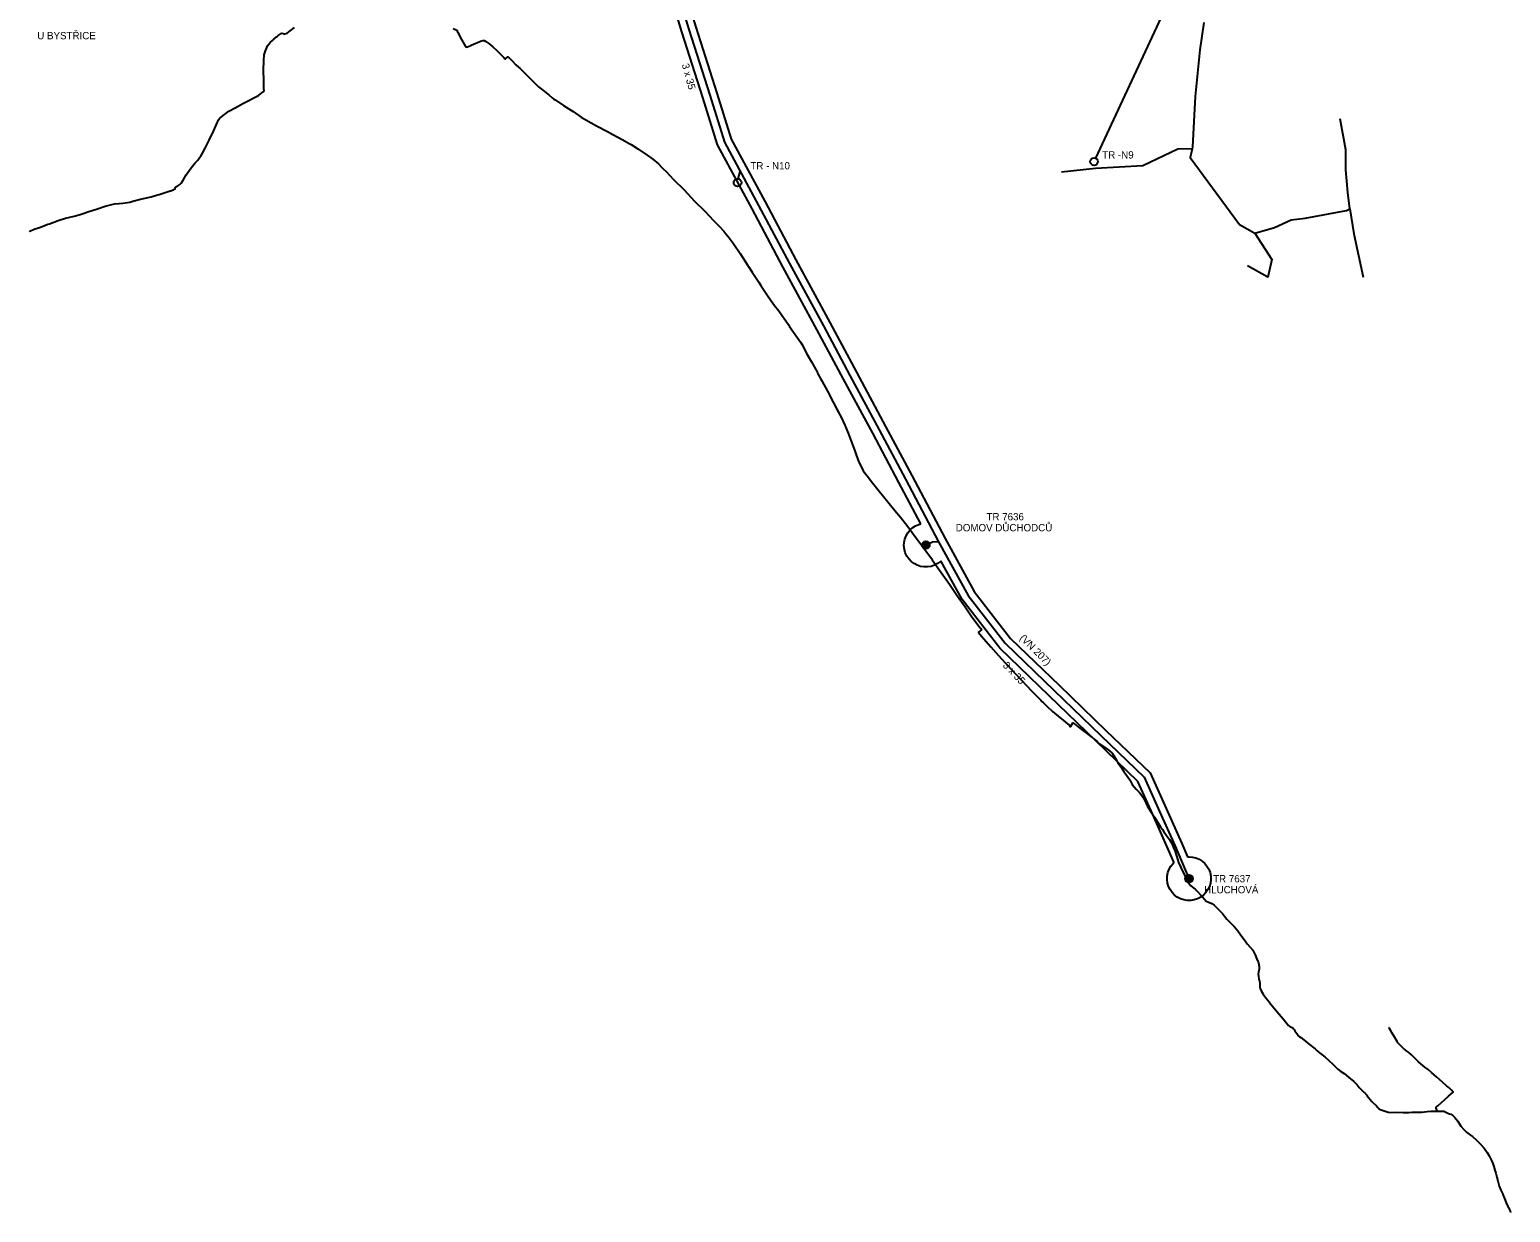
# Model space of a CAD drawing. Extents: x -439095 to -431527, y -1129525 to -1119219.
# Drawn here: x -438464 to -436435, y -1126025 to -1124404 of the extents above; entities that cross this region are included whole.
import ezdxf

# ---------------------------------------------------------------- set-up
doc = ezdxf.new("R2010")
doc.units = 0
for name, color, linetype in [('Hranice reseneho uzemi', 7, 'Continuous'), ('UZEMNI REZERVA', 7, 'Continuous'), ('Vrstva 11', 7, 'Continuous'), ('Vrstva 13', 7, 'Continuous'), ('Vrstva 19', 7, 'Continuous'), ('Vrstva 21', 7, 'Continuous'), ('ZU', 7, 'Continuous')]:
    doc.layers.add(name, color=color, linetype=linetype)

msp = doc.modelspace()

# ---------------------------------------------------------------- linework, layer by layer
at = {"layer": 'Hranice reseneho uzemi'}
msp.add_line((-437493.3, -1124608.4), (-437490.5, -1124598.1), dxfattribs=at)
for points in [[(-437594, -1124294.9), (-437561.1, -1124403.7), (-437532, -1124493.8), (-437512.2, -1124558.1), (-437465.3, -1124644.8), (-437423.1, -1124724.2), (-437376.5, -1124809.9), (-437340.2, -1124878), (-437300.2, -1124952.4), (-437264.2, -1125019.8), (-437218.6, -1125106), (-437178.2, -1125179.2), (-437127.5, -1125244.7), (-437060.5, -1125309.5), (-436996.4, -1125371.4), (-436937.2, -1125428.2), (-436916.2, -1125475.5), (-436894.8, -1125522.9), (-436894.8, -1125522.9), (-436875.7, -1125567.4), (-436875.4, -1125567.4), (-436875.4, -1125567.5)], [(-436908.2, -1124303.4), (-436911.1, -1124380.9), (-437003.6, -1124579.9)], [(-437218.6, -1125106), (-437226.9, -1125106.3), (-437236.2, -1125110.3)]]:
    msp.add_lwpolyline(points, dxfattribs=at)
at = {"layer": 'UZEMNI REZERVA'}
for points in [[(-438464.1, -1124680.4), (-438463.6, -1124680.2), (-438457.8, -1124677.4), (-438449.3, -1124674.4), (-438439.2, -1124670.7), (-438436.8, -1124669.8), (-438430.8, -1124667.6), (-438425, -1124665.5), (-438414.8, -1124662.4), (-438403.1, -1124659.3), (-438395, -1124657), (-438390.8, -1124655.7), (-438384.2, -1124653.6), (-438371, -1124649.4), (-438360.7, -1124646), (-438347.9, -1124642.8), (-438341.6, -1124642), (-438336.4, -1124641.7), (-438326.7, -1124640.1), (-438322.5, -1124639), (-438312.1, -1124636.4), (-438297.6, -1124632.8), (-438290, -1124630.8), (-438286.5, -1124629.8), (-438277, -1124626.8), (-438267, -1124623.4), (-438265.4, -1124622.7), (-438264.8, -1124621.9), (-438264.6, -1124620.2), (-438263.7, -1124619.3), (-438261, -1124618.1), (-438258.3, -1124616.3), (-438256.2, -1124614), (-438253.7, -1124610.2), (-438249.5, -1124603), (-438242.8, -1124593.1), (-438237.3, -1124586.3), (-438233.5, -1124582.9), (-438230.8, -1124578.8), (-438229, -1124576.2), (-438227.1, -1124573.3), (-438223.4, -1124566.5), (-438218.2, -1124555.5), (-438211.6, -1124542.1), (-438207.3, -1124531.7), (-438206.4, -1124529.7), (-438205.4, -1124527.3), (-438203.4, -1124525.1), (-438201.1, -1124523.3), (-438197.2, -1124520), (-438191, -1124515.8), (-438182.3, -1124511.2), (-438171, -1124504.7), (-438163, -1124500.7), (-438161.9, -1124500), (-438158.9, -1124498.2), (-438150.7, -1124494.1), (-438145.9, -1124490.6), (-438144.2, -1124489.1), (-438142.9, -1124487.3), (-438143, -1124485.4), (-438143, -1124482.6), (-438143, -1124478.4), (-438143, -1124473.1), (-438143.6, -1124460), (-438143.3, -1124445.6), (-438142.5, -1124438.2), (-438141.1, -1124433.1), (-438138, -1124426.3), (-438134.5, -1124421.7), (-438131, -1124418.1), (-438129.4, -1124417), (-438125.8, -1124413.9), (-438125, -1124413.2), (-438123.4, -1124411.8), (-438119.3, -1124409.2), (-438118.3, -1124408.8), (-438116.9, -1124409.3), (-438115.6, -1124410.1), (-438114.2, -1124409.8), (-438111.2, -1124408.5), (-438107, -1124405.6), (-438101.3, -1124400.9)], [(-437883.8, -1124402.3), (-437878.9, -1124404.6), (-437878.1, -1124405.8), (-437877.3, -1124407.3), (-437874.3, -1124414.2), (-437866.8, -1124427.2), (-437865.9, -1124427.5), (-437865.1, -1124427.7), (-437864.4, -1124427.4), (-437864.3, -1124427.4), (-437859.4, -1124425.6), (-437859, -1124425.3), (-437858.9, -1124425.3), (-437847.1, -1124420.1), (-437847, -1124420.1), (-437846.9, -1124420), (-437846.6, -1124419.9), (-437846.2, -1124419.7), (-437842.9, -1124418.7), (-437841.5, -1124418.9), (-437839.1, -1124420.3), (-437835.1, -1124423), (-437829.3, -1124427.5), (-437823.9, -1124432.5), (-437818.7, -1124437.6), (-437814.3, -1124442), (-437812.8, -1124443.7), (-437812.4, -1124444), (-437812.1, -1124443.9), (-437809, -1124441), (-437808.7, -1124441), (-437808.1, -1124441.5), (-437807.9, -1124441.7), (-437803, -1124446.6), (-437797.7, -1124451.9), (-437794.2, -1124455.2), (-437792.4, -1124456.9), (-437786.9, -1124462.1), (-437781.5, -1124467.5), (-437775.9, -1124473.1), (-437771.6, -1124477.5), (-437766.7, -1124482.2), (-437761.5, -1124486.5), (-437756.5, -1124490.5), (-437752.7, -1124493.4), (-437748.3, -1124497.2), (-437745.8, -1124499), (-437744.2, -1124500), (-437732.4, -1124507.7), (-437721.6, -1124514.8), (-437719.4, -1124516.2), (-437708.2, -1124523.7), (-437702.1, -1124527.3), (-437687.6, -1124535.5), (-437672.1, -1124543.7), (-437665.2, -1124547.4), (-437658.1, -1124551.2), (-437652.4, -1124554.3), (-437641.7, -1124560.5), (-437639.9, -1124561.5), (-437630.7, -1124567.4), (-437618.1, -1124576.1), (-437610.4, -1124581.6), (-437602.6, -1124588), (-437597.8, -1124592.8), (-437596.1, -1124594.5), (-437592.1, -1124598.5), (-437581.7, -1124609.3), (-437567.4, -1124623.6), (-437553, -1124638.8), (-437540, -1124651.9), (-437532.1, -1124660), (-437527.8, -1124664.5), (-437518.9, -1124673.7), (-437513, -1124680.2), (-437510.1, -1124683.8), (-437507, -1124687.6), (-437500, -1124696.7), (-437499.3, -1124697.7), (-437490.6, -1124710.5), (-437480.2, -1124727), (-437479.2, -1124728.5), (-437474, -1124736.3), (-437465.2, -1124749.9), (-437462.2, -1124754.5), (-437454, -1124766.7), (-437448.1, -1124775.5), (-437443.4, -1124781.8), (-437437.7, -1124789.4), (-437424.1, -1124809), (-437423, -1124810.5), (-437411.9, -1124826.3), (-437407.5, -1124832.6), (-437404.7, -1124837.2), (-437400.2, -1124846.8), (-437392.8, -1124859), (-437384.8, -1124873.9), (-437384, -1124875.4), (-437380, -1124882.8), (-437378.6, -1124885.3), (-437371.1, -1124899.5), (-437362.7, -1124915.2), (-437357.5, -1124925), (-437356.5, -1124927), (-437356.1, -1124927.7), (-437352.3, -1124935), (-437347.3, -1124945.8), (-437342.4, -1124956.9), (-437335.9, -1124975), (-437333.6, -1124981.2), (-437331.6, -1124986.7), (-437327.8, -1124996.5), (-437326, -1125000), (-437321.9, -1125008.3), (-437314.8, -1125017.8), (-437314.8, -1125017.8), (-437314.8, -1125017.8), (-437312.5, -1125020.9), (-437309.4, -1125024.8), (-437300.1, -1125036.3), (-437288.4, -1125050.8), (-437278.6, -1125062.7), (-437270.9, -1125071.9), (-437262, -1125083.2), (-437254.7, -1125093.1), (-437249.7, -1125099.7), (-437238.8, -1125114.5), (-437228.5, -1125128.8), (-437227.5, -1125130.3), (-437215.3, -1125147.8), (-437203.9, -1125163.9), (-437192.8, -1125180.2), (-437182.5, -1125195.1), (-437173, -1125208.6), (-437161.7, -1125223.8), (-437160.9, -1125224.5), (-437160.9, -1125224.5), (-437159.7, -1125226.2), (-437159.9, -1125226.3), (-437163.9, -1125229.5), (-437164.2, -1125229.8), (-437164.1, -1125229.9), (-437159.8, -1125234.9), (-437153.4, -1125242.2), (-437146.9, -1125249.8), (-437140.5, -1125257.3), (-437132.7, -1125266.3), (-437126.7, -1125272.4), (-437125.2, -1125274), (-437118.6, -1125280.7), (-437112.4, -1125287.7), (-437104.9, -1125295.5), (-437098.2, -1125302.5), (-437090.9, -1125310.3), (-437084.2, -1125317.5), (-437078.7, -1125322.9), (-437077.1, -1125324.4), (-437075.4, -1125326.2), (-437070.6, -1125331.1), (-437062.7, -1125338.2), (-437054.8, -1125344.8), (-437047.7, -1125350.7), (-437039.7, -1125356.9), (-437039.4, -1125358), (-437038.8, -1125358.8), (-437038.2, -1125359), (-437038.1, -1125359), (-437037.7, -1125358.9), (-437037.4, -1125358.6), (-437034.7, -1125353.8), (-437034.6, -1125353.7), (-437032.1, -1125355.5), (-437022.9, -1125362.8), (-437018.1, -1125366.5), (-437018, -1125366.6), (-437008.1, -1125374.1), (-437001.5, -1125379.4), (-437000.8, -1125380.1), (-437000.2, -1125381.2), (-436999, -1125382.2), (-436992.9, -1125386.2), (-436988.2, -1125389.7), (-436984.4, -1125392.2), (-436981.1, -1125395.3), (-436978.5, -1125399), (-436975.4, -1125404), (-436972.9, -1125408.6), (-436968.4, -1125414.8), (-436964.8, -1125420.6), (-436961.2, -1125425.7), (-436956.5, -1125432.1), (-436955.3, -1125434.5), (-436955.3, -1125434.5), (-436953.3, -1125438.3), (-436948.2, -1125444.6), (-436944, -1125449), (-436941.6, -1125451.5), (-436938.6, -1125456.1), (-436935.5, -1125461.3), (-436933, -1125467.5), (-436928.4, -1125474.7), (-436922.9, -1125483.1), (-436918.3, -1125490.4), (-436914.5, -1125496.5), (-436912.1, -1125500), (-436909.9, -1125503.3), (-436908.3, -1125505.7), (-436906.6, -1125508.2), (-436902.5, -1125513.8), (-436899.4, -1125518.2), (-436897.2, -1125523.6), (-436895.2, -1125529.3), (-436894.8, -1125530.3), (-436892.8, -1125536.3), (-436889.8, -1125545.2), (-436886.8, -1125551.9), (-436884.2, -1125557.9), (-436881.1, -1125564), (-436879.6, -1125568), (-436875, -1125575.1), (-436873.7, -1125577), (-436870.7, -1125579.2), (-436870.7, -1125579.2), (-436867.3, -1125581.6), (-436856.5, -1125592.7), (-436852.1, -1125598.2), (-436849.7, -1125599.2), (-436844.4, -1125601.6), (-436841.1, -1125603.7), (-436836.2, -1125608.6), (-436829.8, -1125615.2), (-436827, -1125618.8), (-436823.6, -1125623), (-436819.1, -1125627.6), (-436813.3, -1125633.4), (-436808.8, -1125638.9), (-436803.4, -1125646.6), (-436798.8, -1125652.5), (-436796.9, -1125655.2), (-436795.6, -1125657.1), (-436791.6, -1125661.1), (-436788.3, -1125665.4), (-436785, -1125672), (-436782.5, -1125677.7), (-436781.8, -1125679.3), (-436780.6, -1125682.9), (-436779.4, -1125687.8), (-436779.6, -1125691.5), (-436780.3, -1125695.6), (-436780.8, -1125698.4), (-436780.4, -1125701.3), (-436780.1, -1125704.1), (-436779.8, -1125705.7), (-436779.1, -1125707.6), (-436778.7, -1125711.7), (-436778.4, -1125716), (-436778.2, -1125717.8), (-436776.9, -1125721.3), (-436774.2, -1125725.6), (-436770.3, -1125730.9), (-436767.9, -1125733.7), (-436765.9, -1125736.3), (-436763.8, -1125739), (-436761.2, -1125742.2), (-436754.6, -1125749.9), (-436746.8, -1125759.5), (-436739.2, -1125768.6), (-436737.1, -1125770.4), (-436735.2, -1125770.8), (-436733.3, -1125772), (-436732.5, -1125773.1), (-436731.7, -1125774.2), (-436730.8, -1125776.1), (-436727.8, -1125779.8), (-436726.3, -1125782.2), (-436724.8, -1125783.6), (-436722.2, -1125784.9), (-436715.8, -1125790.1), (-436712.2, -1125793.2), (-436702.9, -1125800.7), (-436700, -1125803.3), (-436696.9, -1125806.2), (-436689.6, -1125811.8), (-436684.2, -1125816.4), (-436678.1, -1125821.9), (-436675.4, -1125824.7), (-436674.2, -1125826), (-436671.9, -1125828.3), (-436667.4, -1125831.6), (-436662.9, -1125834.6), (-436657.1, -1125839.4), (-436649.9, -1125845.6), (-436645.4, -1125850), (-436642.4, -1125853.7), (-436639.2, -1125856.8), (-436636.1, -1125859.8), (-436635.8, -1125860.1), (-436632.1, -1125864), (-436631.4, -1125865), (-436629.5, -1125867.5), (-436625, -1125872.9), (-436623.8, -1125874.1), (-436619.4, -1125878.2), (-436617, -1125880.9), (-436615.6, -1125882.6), (-436615.4, -1125882.7), (-436614.4, -1125883.4), (-436612.4, -1125884.3), (-436608.4, -1125885.8), (-436605.3, -1125886.6), (-436602.7, -1125887.4), (-436599.2, -1125887.8), (-436591.3, -1125887.6), (-436582.4, -1125887.8), (-436575.7, -1125887.7), (-436575.6, -1125887.7), (-436574.4, -1125887.7), (-436570.1, -1125887.6), (-436564, -1125887.5), (-436556.4, -1125887.3), (-436549.2, -1125886.7), (-436544.4, -1125886.1), (-436541.8, -1125886.1), (-436536, -1125885.9), (-436533.6, -1125885.9), (-436526.5, -1125885.9), (-436525.6, -1125886.3), (-436520.8, -1125888.7), (-436518.6, -1125889.8), (-436517, -1125890.2), (-436514.1, -1125891.9), (-436511.5, -1125894.5), (-436507.4, -1125899.9), (-436503, -1125906.8), (-436499.2, -1125911.2), (-436495.2, -1125914.9), (-436491.7, -1125917.4), (-436489.9, -1125918.8), (-436487.3, -1125920.9), (-436481.8, -1125925.9), (-436476.6, -1125930.8), (-436471.4, -1125936.6), (-436466.9, -1125942.9), (-436464.5, -1125947.1), (-436463.2, -1125950), (-436460.9, -1125954.6), (-436459.4, -1125957.9), (-436458, -1125961.9), (-436456.5, -1125966.8), (-436455.3, -1125971.2), (-436453.9, -1125976.4), (-436452.4, -1125981.6), (-436450.5, -1125989), (-436448.5, -1125994.4), (-436445.6, -1126000), (-436445.5, -1126000.1), (-436443.2, -1126005.6), (-436440.9, -1126011.5), (-436438.7, -1126016.8), (-436437.6, -1126018.6), (-436436.5, -1126021.1), (-436435.7, -1126022.9), (-436435.3, -1126024.1), (-436435.6, -1126024.8)], [(-436855.2, -1124394.3), (-436860.8, -1124431.4), (-436863.9, -1124463.4), (-436867, -1124495.5), (-436868.8, -1124530), (-436870.7, -1124564.6), (-436871.3, -1124567.4), (-436873.8, -1124579.3), (-436806.5, -1124670.8), (-436785.3, -1124682.8), (-436758.5, -1124674.9), (-436735.5, -1124664.5), (-436716.5, -1124662.4), (-436659.7, -1124651.6), (-436655.2, -1124649.3), (-436649.7, -1124683.9), (-436637.2, -1124742.9)], [(-436655.2, -1124649.3), (-436658.1, -1124627.2), (-436660.8, -1124596), (-436660.8, -1124568.8), (-436668.4, -1124525.9)], [(-436871.3, -1124567.4), (-436890.7, -1124567.8), (-436938.7, -1124590.6), (-436971.2, -1124592.4), (-437003.7, -1124594.3), (-437050.4, -1124599.4)], [(-436785.3, -1124682.8), (-436762, -1124718.8), (-436767.7, -1124743.1), (-436795.4, -1124727.6)], [(-436536, -1125885.9), (-436536.1, -1125884.4), (-436536.9, -1125882.1), (-436536.8, -1125881.2), (-436536.4, -1125880.2), (-436534.6, -1125878.7), (-436529.7, -1125874.3), (-436525.7, -1125870.4), (-436520.2, -1125865.4), (-436513.7, -1125859.8), (-436516.2, -1125857.2), (-436518, -1125855.4), (-436519.8, -1125853.8), (-436522.5, -1125851.6), (-436528.5, -1125846.1), (-436536.1, -1125839.3), (-436543.3, -1125832.9), (-436548, -1125829.1), (-436552.6, -1125825.9), (-436558, -1125821.4), (-436561.2, -1125818.4), (-436563.6, -1125816.1), (-436565.4, -1125814.3), (-436568.7, -1125811), (-436571, -1125808.8), (-436574.5, -1125805.8), (-436579, -1125802.4), (-436580.4, -1125801.2), (-436581.7, -1125800.1), (-436583.2, -1125798.8), (-436585.4, -1125796.7), (-436587.2, -1125794.8), (-436589.3, -1125792.4), (-436590.2, -1125790.8), (-436593.6, -1125785), (-436597.1, -1125779.1), (-436599.5, -1125775.1), (-436601.1, -1125772.6), (-436601.3, -1125772.2), (-436601.5, -1125771.9), (-436601.8, -1125771.2)]]:
    msp.add_lwpolyline(points, dxfattribs=at)
at = {"layer": 'Vrstva 11'}
for centre, radius in [((-437236.2, -1125110.3), 5.25), ((-437236.2, -1125110.3), 4.55), ((-437236.2, -1125110.3), 3.85), ((-437236.2, -1125110.3), 3.15), ((-437236.2, -1125110.3), 2.45), ((-437236.2, -1125110.3), 1.75), ((-437236.2, -1125110.3), 1.05), ((-437236.2, -1125110.3), 0.35), ((-436875.6, -1125567.4), 5.25), ((-436875.6, -1125567.4), 4.55), ((-436875.6, -1125567.4), 3.85), ((-436875.6, -1125567.4), 3.15), ((-436875.6, -1125567.4), 2.45), ((-436875.6, -1125567.4), 1.75), ((-436875.6, -1125567.4), 1.05), ((-436875.6, -1125567.4), 0.35)]:
    msp.add_circle(centre, radius, dxfattribs=at)
at = {"layer": 'Vrstva 19'}
for centre in [(-437005.7, -1124584.7), (-437494.2, -1124613.6)]:
    msp.add_circle(centre, 5.25, dxfattribs=at)
at = {"layer": 'ZU'}
for points in [[(-437243, -1125081.2), (-437273, -1125024.5), (-437309, -1124957.1), (-437349.1, -1124882.8), (-437385.3, -1124814.7), (-437431.9, -1124729), (-437474.1, -1124649.5), (-437521.4, -1124561.9), (-437541.6, -1124496.8), (-437570.6, -1124406.7), (-437603, -1124299.7)], [(-437580.4, -1124305.5), (-437551.5, -1124400.7), (-437522.5, -1124490.8), (-437502.9, -1124554.2), (-437456.4, -1124640), (-437414.3, -1124719.5), (-437367.7, -1124805.2), (-437331.4, -1124873.3), (-437291.4, -1124947.6), (-437255.4, -1125015.1), (-437209.8, -1125101.2), (-437169.8, -1125173.7), (-437120, -1125238.1), (-437053.5, -1125302.3), (-436989.5, -1125364.2), (-436928.9, -1125422.4), (-436907.1, -1125471.4), (-436885.5, -1125519.2), (-436885.5, -1125519.3), (-436877.6, -1125537.6)], [(-437215.6, -1125132), (-437216.3, -1125132.8), (-437220.2, -1125135.7), (-437224.5, -1125137.9), (-437229, -1125139.4), (-437233.8, -1125140.2), (-437238.6, -1125140.2), (-437243.4, -1125139.4), (-437248, -1125137.9), (-437252.2, -1125135.7), (-437256.1, -1125132.8), (-437259.4, -1125129.3), (-437262.2, -1125125.3), (-437264.3, -1125121), (-437265.6, -1125116.3), (-437266.2, -1125111.5), (-437266, -1125106.7), (-437265, -1125102), (-437263.3, -1125097.5), (-437260.9, -1125093.3), (-437257.8, -1125089.5), (-437254.2, -1125086.3), (-437250.2, -1125083.8), (-437245.7, -1125081.9), (-437243, -1125081.2)], [(-436896, -1125545.5), (-436904, -1125526.9), (-436925.3, -1125479.6), (-436945.5, -1125434.1), (-437003.3, -1125378.6), (-437067.4, -1125316.7), (-437134.9, -1125251.4), (-437186.6, -1125184.7), (-437215.6, -1125132)], [(-436877.6, -1125537.6), (-436875.6, -1125537.4), (-436870.8, -1125537.8), (-436866.1, -1125539), (-436861.7, -1125540.9), (-436857.6, -1125543.4), (-436854, -1125546.6), (-436851, -1125550.4), (-436848.5, -1125554.6), (-436846.8, -1125559.1), (-436845.9, -1125563.8), (-436845.7, -1125568.6), (-436846.3, -1125573.4), (-436847.6, -1125578.1), (-436849.7, -1125582.4), (-436852.4, -1125586.4), (-436855.8, -1125589.9), (-436859.6, -1125592.8), (-436863.9, -1125595), (-436868.5, -1125596.5), (-436873.2, -1125597.3), (-436878.1, -1125597.3), (-436882.8, -1125596.5), (-436887.4, -1125595), (-436891.7, -1125592.8), (-436895.5, -1125589.9), (-436898.9, -1125586.4), (-436901.6, -1125582.4), (-436903.7, -1125578.1), (-436905, -1125573.4), (-436905.6, -1125568.6), (-436905.4, -1125563.8), (-436904.5, -1125559.1), (-436902.8, -1125554.6), (-436900.3, -1125550.4), (-436897.3, -1125546.6), (-436896, -1125545.5)]]:
    msp.add_lwpolyline(points, dxfattribs=at)

# ---------------------------------------------------------------- texts
at = {"layer": 'Vrstva 13'}
for s, p in [('U BYSTŘICE', (-438453.6, -1124417.1)), ('TR 7636', (-437153.1, -1125076.4)), ('DOMOV DŮCHODCŮ', (-437195.2, -1125091.4)), ('HLUCHOVÁ', (-436854.9, -1125587.5)), ('TR 7637', (-436842.6, -1125572.5))]:
    msp.add_text(s, height=10, dxfattribs=at).set_placement(p)
for s, rotation, p in [('3 x 35', 285.4663, (-437570.7, -1124451.8)), ('(VN 207)', 315.1787, (-437108.4, -1125238.5)), ('3 x 35', 314.0312, (-437131.5, -1125275.9))]:
    msp.add_text(s, height=10, rotation=rotation, dxfattribs=at).set_placement(p)
at = {"layer": 'Vrstva 21'}
for s, p in [('TR - N10', (-437476.6, -1124595.4)), ('TR -N9', (-436994.5, -1124580.5))]:
    msp.add_text(s, height=10, dxfattribs=at).set_placement(p)

doc.saveas('drawing.dxf')
